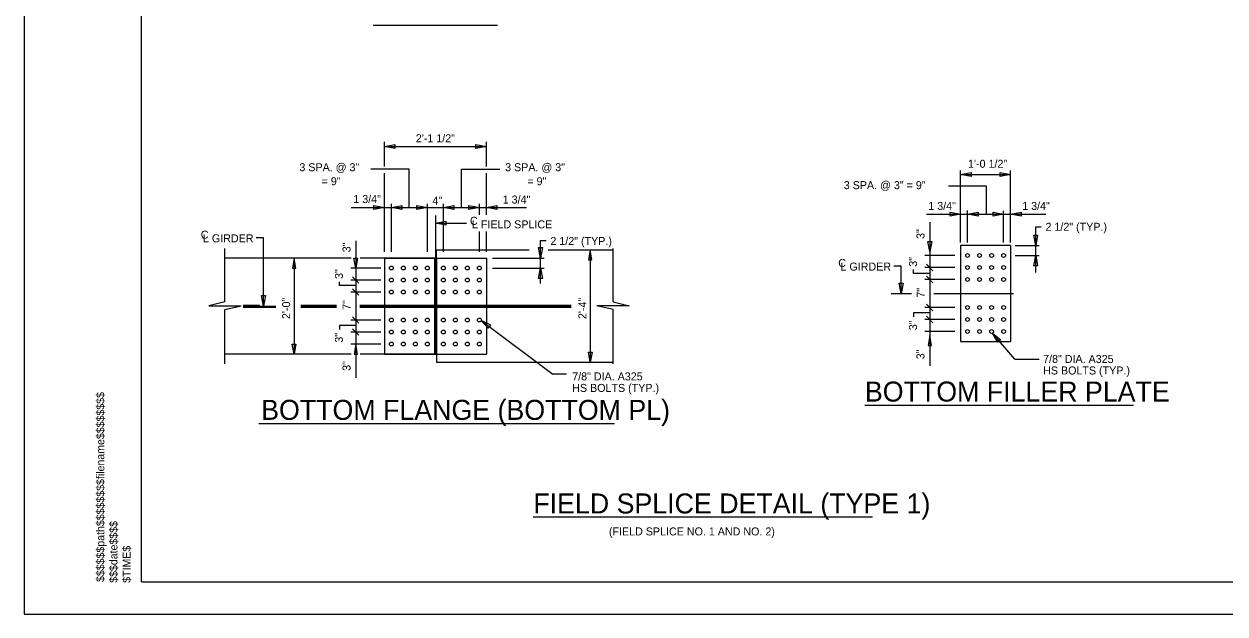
# Model space of a CAD drawing. Extents: x -448.1 to -400, y -140.7 to -111.4.
# Drawn here: x -448.13 to -423.13, y -140.7 to -128.41 of the extents above; entities that cross this region are included whole.
import ezdxf

# ---------------------------------------------------------------- set-up
doc = ezdxf.new("R2010")
doc.units = 0
for name, color, linetype in [('BR_AUTO DIMENSION', 7, 'Continuous'), ('BR_BORDER LINES', 7, 'Continuous'), ('BR_CENTER LINES', 7, 'Continuous'), ('BR_STRUCTURAL STEEL', 7, 'Continuous'), ('BR_TEXT', 7, 'Continuous'), ('Default', 7, 'Continuous'), ('Level 31', 7, 'Continuous'), ('RD_SHT_ID', 7, 'Continuous')]:
    doc.layers.add(name, color=color, linetype=linetype)

msp = doc.modelspace()

# ---------------------------------------------------------------- linework, layer by layer
at = {"layer": 'BR_AUTO DIMENSION'}
for p, q in [((-440.631, -131.382), (-440.631, -130.866)), ((-440.631, -130.965), (-438.506, -130.965)), ((-438.506, -131.382), (-438.506, -130.866)), ((-440.631, -133.159), (-440.631, -131.517)), ((-438.506, -132.39), (-438.506, -131.517)), ((-428.633, -132.966), (-428.633, -131.464)), ((-427.591, -132.966), (-427.591, -131.464)), ((-428.633, -131.545), (-427.591, -131.545)), ((-441.321, -132.235), (-437.67, -132.235)), ((-440.485, -133.159), (-440.485, -132.16)), ((-439.735, -133.159), (-439.735, -132.16)), ((-439.402, -133.159), (-439.402, -132.16)), ((-438.652, -132.39), (-438.652, -132.16)), ((-429.345, -132.376), (-426.861, -132.376)), ((-428.487, -132.966), (-428.487, -132.298)), ((-427.737, -132.966), (-427.737, -132.306)), ((-438.652, -133.159), (-438.652, -132.732)), ((-438.506, -133.159), (-438.506, -132.732)), ((-429.275, -132.539), (-429.275, -135.534)), ((-427.069, -133.586), (-427.069, -132.64)), ((-427.069, -132.64), (-426.953, -132.64)), ((-443.145, -132.868), (-443.299, -132.868)), ((-443.145, -134.286), (-443.145, -132.868)), ((-441.228, -132.926), (-441.228, -135.781)), ((-437.38, -133.82), (-437.38, -132.924)), ((-437.38, -132.924), (-437.263, -132.924)), ((-427.496, -133.025), (-426.995, -133.025)), ((-436.343, -133.119), (-436.343, -135.452)), ((-428.751, -133.233), (-429.376, -133.233)), ((-427.496, -133.233), (-426.995, -133.233)), ((-442.511, -133.286), (-442.511, -135.286)), ((-440.704, -133.494), (-441.329, -133.494)), ((-438.382, -133.286), (-437.305, -133.286)), ((-438.382, -133.494), (-437.305, -133.494)), ((-429.871, -133.457), (-430.026, -133.457)), ((-429.871, -134.025), (-429.871, -133.457)), ((-428.751, -133.483), (-429.376, -133.483)), ((-429.209, -133.551), (-429.341, -133.416)), ((-440.704, -133.744), (-441.329, -133.744)), ((-441.161, -133.811), (-441.294, -133.677)), ((-428.751, -133.733), (-429.376, -133.733)), ((-429.209, -133.801), (-429.341, -133.666)), ((-440.704, -133.994), (-441.329, -133.994)), ((-441.161, -134.061), (-441.294, -133.927)), ((-429.209, -134.384), (-429.341, -134.249)), ((-441.161, -134.645), (-441.294, -134.51)), ((-428.751, -134.316), (-429.376, -134.316)), ((-429.209, -134.634), (-429.341, -134.499)), ((-440.704, -134.577), (-441.329, -134.577)), ((-441.161, -134.895), (-441.294, -134.76)), ((-438.614, -134.586), (-437.124, -135.707)), ((-428.751, -134.566), (-429.376, -134.566)), ((-440.704, -134.827), (-441.329, -134.827)), ((-428.751, -134.816), (-429.376, -134.816)), ((-427.506, -135.389), (-427.966, -134.849)), ((-440.704, -135.077), (-441.329, -135.077)), ((-427.506, -135.389), (-427, -135.389)), ((-436.838, -135.707), (-437.124, -135.707))]:
    msp.add_line(p, q, dxfattribs=at)
for points in [[(-440.415, -131.007), (-440.631, -130.965), (-440.415, -130.923)], [(-438.723, -130.923), (-438.506, -130.965), (-438.723, -131.007)], [(-428.416, -131.587), (-428.633, -131.545), (-428.416, -131.503)], [(-427.808, -131.503), (-427.591, -131.545), (-427.808, -131.587)], [(-440.848, -132.193), (-440.631, -132.235), (-440.848, -132.277)], [(-440.269, -132.277), (-440.485, -132.235), (-440.269, -132.193)], [(-439.952, -132.193), (-439.735, -132.235), (-439.952, -132.277)], [(-439.185, -132.277), (-439.402, -132.235), (-439.185, -132.193)], [(-438.869, -132.193), (-438.652, -132.235), (-438.869, -132.277)], [(-438.29, -132.277), (-438.506, -132.235), (-438.29, -132.193)], [(-439.352, -132.599), (-439.569, -132.557), (-439.352, -132.516)], [(-428.849, -132.334), (-428.633, -132.376), (-428.849, -132.417)], [(-428.27, -132.417), (-428.487, -132.376), (-428.27, -132.334)], [(-427.954, -132.334), (-427.737, -132.376), (-427.954, -132.417)], [(-427.374, -132.417), (-427.591, -132.376), (-427.374, -132.334)], [(-429.235, -132.942), (-429.275, -133.15), (-429.315, -132.942)], [(-427.028, -132.808), (-427.069, -133.025), (-427.111, -132.808)], [(-437.338, -133.069), (-437.38, -133.286), (-437.421, -133.069)], [(-436.378, -133.327), (-436.308, -133.327), (-436.343, -133.119)], [(-427.111, -133.45), (-427.069, -133.233), (-427.028, -133.45)], [(-442.546, -133.494), (-442.476, -133.494), (-442.511, -133.286)], [(-441.188, -133.286), (-441.228, -133.494), (-441.268, -133.286)], [(-437.421, -133.711), (-437.38, -133.494), (-437.338, -133.711)], [(-429.83, -133.808), (-429.871, -134.025), (-429.913, -133.808)], [(-443.103, -134.069), (-443.145, -134.286), (-443.186, -134.069)], [(-438.416, -134.683), (-438.614, -134.586), (-438.466, -134.749)], [(-429.31, -135.108), (-429.24, -135.108), (-429.275, -134.9)], [(-427.857, -135.041), (-427.966, -134.849), (-427.794, -134.987)], [(-442.471, -135.078), (-442.511, -135.286), (-442.551, -135.078)], [(-441.262, -135.286), (-441.193, -135.286), (-441.228, -135.077)], [(-436.303, -135.244), (-436.343, -135.452), (-436.383, -135.244)]]:
    msp.add_lwpolyline(points, close=True, dxfattribs=at)
for points in [[(-440.113, -132.235), (-440.113, -131.439), (-440.91, -131.439)], [(-440.113, -132.235), (-440.113, -131.439), (-440.91, -131.439)], [(-439.024, -132.235), (-439.024, -131.439), (-438.228, -131.439)], [(-428.091, -132.376), (-428.091, -131.789), (-428.887, -131.789)], [(-439.569, -132.557), (-438.921, -132.557)], [(-429.275, -133.606), (-429.612, -133.606), (-429.612, -133.525)], [(-441.228, -133.861), (-441.565, -133.861), (-441.565, -133.779)], [(-429.275, -134.43), (-429.612, -134.43), (-429.612, -134.512)], [(-441.228, -134.694), (-441.565, -134.694), (-441.565, -134.776)]]:
    msp.add_lwpolyline(points, dxfattribs=at)
at = {"layer": 'BR_BORDER LINES'}
for q in [(-445.689, -112.031), (-400.801, -140.031)]:
    msp.add_line((-445.689, -140.031), q, dxfattribs=at)
at = {"layer": 'BR_CENTER LINES'}
for p, q in [((-439.569, -132.401), (-439.569, -135.286)), ((-430.079, -134.025), (-429.656, -134.025)), ((-429.19, -134.025), (-427.528, -134.025)), ((-443.568, -134.286), (-442.892, -134.286)), ((-442.371, -134.286), (-441.627, -134.286)), ((-441.142, -134.286), (-436.742, -134.286))]:
    msp.add_line(p, q, dxfattribs=at)
at = {"layer": 'BR_STRUCTURAL STEEL'}
for p, q in [((-428.633, -133.025), (-428.633, -135.025)), ((-427.591, -133.025), (-428.633, -133.025)), ((-427.591, -133.025), (-427.591, -135.025)), ((-439.548, -133.286), (-439.548, -133.119)), ((-439.548, -133.119), (-437.614, -133.119)), ((-437.22, -133.119), (-435.869, -133.119)), ((-441.323, -133.286), (-443.95, -133.286)), ((-439.548, -133.286), (-441.132, -133.286)), ((-440.631, -133.286), (-438.506, -133.286)), ((-440.631, -133.286), (-440.631, -135.286)), ((-439.59, -133.286), (-439.59, -135.286)), ((-439.548, -133.286), (-439.548, -135.286)), ((-438.506, -133.286), (-438.506, -135.286)), ((-443.568, -134.265), (-443.227, -134.265)), ((-442.371, -134.265), (-441.627, -134.265)), ((-441.142, -134.265), (-439.59, -134.265)), ((-439.548, -134.265), (-436.742, -134.265)), ((-443.568, -134.306), (-442.892, -134.306)), ((-442.371, -134.306), (-441.627, -134.306)), ((-441.142, -134.306), (-439.59, -134.306)), ((-439.548, -134.306), (-436.742, -134.306)), ((-428.633, -135.025), (-427.591, -135.025)), ((-441.323, -135.286), (-443.95, -135.286)), ((-439.59, -135.286), (-441.132, -135.286)), ((-440.631, -135.286), (-438.506, -135.286)), ((-439.548, -135.286), (-439.548, -135.452)), ((-439.548, -135.452), (-435.869, -135.452))]:
    msp.add_line(p, q, dxfattribs=at)
for centre in [(-428.487, -133.233), (-428.487, -133.233), (-428.237, -133.233), (-428.237, -133.233), (-427.987, -133.233), (-427.987, -133.233), (-427.737, -133.233), (-427.737, -133.233), (-440.485, -133.494), (-440.485, -133.494), (-440.235, -133.494), (-440.235, -133.494), (-439.985, -133.494), (-439.985, -133.494), (-439.735, -133.494), (-439.735, -133.494), (-439.402, -133.494), (-439.402, -133.494), (-439.152, -133.494), (-439.152, -133.494), (-438.902, -133.494), (-438.902, -133.494), (-438.652, -133.494), (-438.652, -133.494), (-428.487, -133.483), (-428.487, -133.483), (-428.237, -133.483), (-428.237, -133.483), (-427.987, -133.483), (-427.987, -133.483), (-427.737, -133.483), (-427.737, -133.483), (-440.485, -133.744), (-440.485, -133.744), (-440.235, -133.744), (-440.235, -133.744), (-439.985, -133.744), (-439.985, -133.744), (-439.735, -133.744), (-439.735, -133.744), (-439.402, -133.744), (-439.402, -133.744), (-439.152, -133.744), (-439.152, -133.744), (-438.902, -133.744), (-438.902, -133.744), (-438.652, -133.744), (-438.652, -133.744), (-428.487, -133.733), (-428.487, -133.733), (-428.237, -133.733), (-428.237, -133.733), (-427.987, -133.733), (-427.987, -133.733), (-427.737, -133.733), (-427.737, -133.733), (-440.485, -133.994), (-440.485, -133.994), (-440.235, -133.994), (-440.235, -133.994), (-439.985, -133.994), (-439.985, -133.994), (-439.735, -133.994), (-439.735, -133.994), (-439.402, -133.994), (-439.402, -133.994), (-439.152, -133.994), (-439.152, -133.994), (-438.902, -133.994), (-438.902, -133.994), (-438.652, -133.994), (-438.652, -133.994), (-428.487, -134.316), (-428.487, -134.316), (-428.237, -134.316), (-428.237, -134.316), (-427.987, -134.316), (-427.987, -134.316), (-427.737, -134.316), (-427.737, -134.316), (-428.487, -134.566), (-428.487, -134.566), (-428.237, -134.566), (-428.237, -134.566), (-427.987, -134.566), (-427.987, -134.566), (-427.737, -134.566), (-427.737, -134.566), (-440.485, -134.577), (-440.485, -134.577), (-440.235, -134.577), (-440.235, -134.577), (-439.985, -134.577), (-439.985, -134.577), (-439.735, -134.577), (-439.735, -134.577), (-439.402, -134.577), (-439.402, -134.577), (-439.152, -134.577), (-439.152, -134.577), (-438.902, -134.577), (-438.902, -134.577), (-438.652, -134.577), (-438.652, -134.577), (-428.487, -134.816), (-428.487, -134.816), (-428.237, -134.816), (-428.237, -134.816), (-427.987, -134.816), (-427.987, -134.816), (-427.737, -134.816), (-427.737, -134.816), (-440.485, -134.827), (-440.485, -134.827), (-440.235, -134.827), (-440.235, -134.827), (-439.985, -134.827), (-439.985, -134.827), (-439.735, -134.827), (-439.735, -134.827), (-439.402, -134.827), (-439.402, -134.827), (-439.152, -134.827), (-439.152, -134.827), (-438.902, -134.827), (-438.902, -134.827), (-438.652, -134.827), (-438.652, -134.827), (-440.485, -135.077), (-440.485, -135.077), (-440.235, -135.077), (-440.235, -135.077), (-439.985, -135.077), (-439.985, -135.077), (-439.735, -135.077), (-439.735, -135.077), (-439.402, -135.077), (-439.402, -135.077), (-439.152, -135.077), (-439.152, -135.077), (-438.902, -135.077), (-438.902, -135.077), (-438.652, -135.077), (-438.652, -135.077)]:
    msp.add_circle(centre, 0.0391, dxfattribs=at)
at = {"layer": 'BR_TEXT'}
for p, q in [((-440.865, -128.436), (-438.272, -128.436)), ((-430.628, -136.349), (-425.035, -136.349)), ((-443.247, -136.729), (-435.836, -136.729)), ((-437.532, -138.678), (-430.466, -138.678))]:
    msp.add_line(p, q, dxfattribs=at)
at = {"layer": 'Default'}
for p, q in [((-443.95, -134.198), (-443.95, -133.089)), ((-435.869, -134.198), (-435.869, -133.089)), ((-435.869, -134.198), (-435.869, -133.089)), ((-443.95, -134.198), (-444.285, -134.279)), ((-444.285, -134.279), (-443.614, -134.279)), ((-443.95, -134.359), (-443.614, -134.279)), ((-435.534, -134.279), (-436.205, -134.279)), ((-435.869, -134.359), (-436.205, -134.279)), ((-435.534, -134.279), (-436.205, -134.279)), ((-435.869, -134.359), (-436.205, -134.279)), ((-435.869, -134.198), (-435.534, -134.279)), ((-435.869, -134.198), (-435.534, -134.279)), ((-443.95, -135.488), (-443.95, -134.359)), ((-435.869, -135.488), (-435.869, -134.359)), ((-435.869, -135.488), (-435.869, -134.359))]:
    msp.add_line(p, q, dxfattribs=at)
at = {"layer": 'Level 31'}
msp.add_lwpolyline([(-448.133, -140.698), (-400.133, -140.698), (-400.133, -111.364), (-448.133, -111.364)], close=True, dxfattribs=at)

# ---------------------------------------------------------------- texts
at = {"layer": 'BR_TEXT'}
for s, height, p in [('2\'-1 1/2"', 0.1667, (-439.976, -130.876)), ('1\'-0 1/2"', 0.1667, (-428.478, -131.407)), ('3 SPA. @ 3" ', 0.16667, (-442.4, -131.479)), ('3 SPA. @ 3" ', 0.16667, (-438.116, -131.479)), ('= 9"', 0.1667, (-441.937, -131.771)), ('= 9"', 0.1667, (-437.653, -131.771)), ('3 SPA. @ 3" = 9"', 0.16667, (-431.065, -131.852)), ('1 3/4"', 0.1667, (-441.277, -132.141)), ('4"', 0.1667, (-439.63, -132.172)), ('1 3/4"', 0.1667, (-438.166, -132.152)), ('1 3/4"', 0.1667, (-429.305, -132.285)), ('1 3/4"', 0.1667, (-427.35, -132.285)), ('C', 0.167, (-438.849, -132.596)), ('L FIELD SPLICE', 0.16667, (-438.807, -132.669)), ('C', 0.167, (-444.453, -132.884)), ('2 1/2" (TYP.)', 0.16667, (-426.865, -132.719)), ('L GIRDER', 0.1667, (-444.408, -132.959)), ('2 1/2" (TYP.)', 0.16667, (-437.173, -133.015)), ('C', 0.167, (-431.18, -133.473)), ('L GIRDER', 0.1667, (-431.134, -133.548)), ('7/8" DIA. A325', 0.16667, (-426.914, -135.471)), ('7/8" DIA. A325', 0.16667, (-436.719, -135.834)), ('HS BOLTS (TYP.)', 0.16667, (-426.914, -135.711)), ('HS BOLTS (TYP.)', 0.16667, (-436.719, -136.074)), ('BOTTOM FILLER PLATE', 0.41667, (-430.625, -136.275)), ('BOTTOM FLANGE (BOTTOM PL)', 0.41667, (-443.196, -136.656)), ('FIELD SPLICE DETAIL (TYPE 1)', 0.41667, (-437.529, -138.605)), ('(FIELD SPLICE NO. 1 AND NO. 2)', 0.16667, (-435.955, -139.062))]:
    msp.add_text(s, height=height, dxfattribs=at).set_placement(p)
for s, p in [('3"', (-429.385, -132.889)), ('3"', (-441.335, -133.167)), ('3"', (-429.54, -133.468)), ('3"', (-441.493, -133.722)), ('7"', (-429.378, -134.112)), ('2\'-0"', (-442.592, -134.557)), ('7"', (-441.335, -134.365)), ('2\'-4"', (-436.424, -134.557)), ('3"', (-429.54, -134.789)), ('3"', (-441.493, -135.049)), ('3"', (-429.385, -135.394)), ('3"', (-441.335, -135.635))]:
    msp.add_text(s, height=0.1667, rotation=90, dxfattribs=at).set_placement(p)
at = {"layer": 'RD_SHT_ID'}
for s, height, p in [('$$$$$$path$$$$$$$$filename$$$$$$$$', 0.16462, (-446.462, -140.031)), ('$$$date$$$$', 0.16462, (-446.188, -140.048)), ('$TIME$', 0.1646, (-445.915, -140.048))]:
    msp.add_text(s, height=height, rotation=90, dxfattribs=at).set_placement(p)

doc.saveas('drawing.dxf')
